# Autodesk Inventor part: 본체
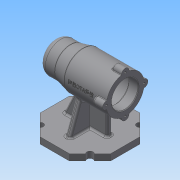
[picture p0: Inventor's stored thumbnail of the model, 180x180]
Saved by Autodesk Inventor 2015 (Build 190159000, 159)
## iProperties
Created: 2019-12
Part Number: 본체
Material: 일반
Document SubType Name: Modeling
Designer: user
Density: 1 g/cm^3
Appearance: 기본값
Mass: 268.496 g
Surface Area: 715.535 cm^2
Volume: 268.496 cm^3
Author: user
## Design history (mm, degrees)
sketch "스케치1"
  geometry: L1 (-56, 0)-(56, 0); L2 (56, 0)-(56, 21); L3 (56, 21)-(41, 21); L4 (41, 21)-(41, 24); L5 (41, 24)-(-13, 24); L6 (-13, 24)-(-13, 21); L7 (-13, 21)-(-25, 21); L8 (-25, 21)-(-25, 17.5); L9 (-25, 17.5)-(-43, 17.5); L10 (-43, 17.5)-(-43, 16); L11 (-43, 16)-(-47, 16); L12 (-47, 16)-(-47, 10.5); L13 (-47, 10.5)-(-50, 10.5); L14 (-50, 10.5)-(-50, 0); L15 (-56, 0)-(-56, 25); L16 (56, 21)-(56, 30); L17 (-56, 25)-(-31, 25); L18 (-31, 25)-(-11, 30); L19 (-11, 30)-(56, 30); 2 further points
  constraints: 38 end point, 10 perpendicular, 4 vertical, 3 point on line, 2 horizontal, 1 coincident, 1 midpoint
  dimensions: "d1" = 112 distance of L1.start L1.end; "d2" = 42 diameter of L3 L1; "d3" = 48 diameter of L5 L1; "d4" = 35 diameter of L9 L1; "d5" = 32 diameter of L11 L1; "d6" = 21 diameter of L13 L1; "d7" = 15 distance of L2.end L3.end; "d8" = 54 distance of L4.end L5.end; "d9" = 12 distance of L6.end L7.end; "d10" = 18 distance of L8.end L9.end; "d11" = 4 distance of L10.end L11.end; "d12" = 3 distance of L12.end L13.end; "d13" = 50 diameter of L15.end L1; "d14" = 60 diameter of L16.end L1; "d18" = 60 diameter of L18.end L1; "d19" = 25 distance of L15.end L17.end; "d20" = 45 horizontal distance of L18.end L15.end
revolve "회전1" sketch "스케치1" stored, may be unused: angle "d21" = 90 deg
fillet "모깎기1" dims "d22" = 3
fillet "모깎기2" dims "d23" = 3
chamfer "모따기1" distance "d24" = 1; stored, may be unused: second distance "d25" = 2, angle "d26" = 45 deg
sketch "스케치2"
  geometry: A1 r 6 centre (-30, 0) between (-29.4, 5.97) and (-29.4, -5.97); A2 r 6 centre (0, -30) between (-5.97, -29.4) and (5.97, -29.4); A3 r 6 centre (0, 30) between (5.97, 29.4) and (-5.97, 29.4); A4 r 6 centre (30, 0) between (29.4, -5.97) and (29.4, 5.97); 1 further point
  constraints: 8 point on circle, 4 centre point, 13 other
  dimensions: "d33" = 6 radius of A1; "d34" = 6 radius of A2; "d35" = 6 radius of A4; "d36" = 6 radius of A3; "d37" = 60 distance of A3.centre A2.centre; "d38" = 60 distance of A1.centre A4.centre; "d39" = 30 horizontal distance of A1.centre A3.centre; "d40" = 30 horizontal distance of A1.centre A2.centre
extrude "돌출1" join sketch "스케치2" distance "d41" = 16; taper "d42" = 0 deg
node "작업 평면1"
sketch "스케치5"
  geometry: A1 r 6 centre (0, 0) between (0.6, 5.97) and (0.6, -5.97) reference; A2 r 6 centre (30, -30) between (24.03, -29.4) and (35.97, -29.4) reference; A3 r 6 centre (60, 0) between (59.4, -5.97) and (59.4, 5.97) reference; A4 r 6 centre (30, 30) between (35.97, 29.4) and (24.03, 29.4) reference; 4 further points
  constraints: 4 coincident
hole "구멍1" sketch "스케치5" at (0, 0), (30, -30), (30, 30), (60, 0) diameter "d52" = 3.242; stored, may be unused: countersink angle "d56" = 90 deg, drill point angle "d58" = 118 deg; dims "d53" = 8, "d54" = 4, "d55" = 2, "d57" = 11
sketch "스케치6" dims "d60" = 112
  geometry: L1 (23.196, 56)-(56, 23.196); L2 (56, 23.196)-(56, -23.196); L3 (56, -23.196)-(23.196, -56); L4 (23.196, -56)-(-23.196, -56); L5 (-23.196, -56)-(-56, -23.196); L6 (-56, -23.196)-(-56, 23.196); L7 (-56, 23.196)-(-23.196, 56); L8 (-23.196, 56)-(23.196, 56); L9 (0, 0)-(0, 56); 3 further points
  constraints: 18 end point, 2 coincident, 2 midpoint, 1 vertical, 1 vertical alignment, 19 other
extrude "돌출3" join sketch "스케치6" distance "d61" = 10; taper "d62" = 0 deg
sketch "스케치8"
  geometry: L1 (-23.196, -70)-(-56, -70) reference; L2 (56, -70)-(23.196, -70) reference; L3 (36, -70)-(18.979, -23.234); L4 (-36, -70)-(-18.979, -23.234); L5 (-36, -70)-(36, -70); A1 r 30 centre (0, 0) between (18.979, -23.234) and (-18.979, -23.234) reference; A2 r 30 centre (0, 0) between (-18.979, -23.234) and (18.979, -23.234); 1 further point
  constraints: 6 end point, 4 point on circle, 2 point on line, 1 centre point, 1 coincident, 1 collinear, 1 concentric
  dimensions: "d68" = 110 deg angle of L2 L3; "d69" = 20 distance of L2.start L3.start; "d70" = 110 deg angle of L1 L4; "d71" = 20 distance of L1.end L4.start
extrude "돌출4" join sketch "스케치8" stored distance "d72" = 8; taper "d73" = 0 deg
sketch "스케치9"
  geometry: L1 (-56, -70)-(-23.196, -70) reference; L2 (11, -30)-(-40, -30) reference; L3 (31, -25)-(11, -30) reference; L4 (23.196, -70)-(56, -70) reference; L5 (38, -70)-(18.476, -28.131); L6 (-31, -70)-(-31, -30); 1 further point
  constraints: 4 end point, 4 point on line, 1 vertical
  dimensions: "d74" = 115 deg angle of L4 L5; "d75" = 18 distance of L4.end L5.start; "d76" = 25 distance from line of L1.start L6
feature "리브1" sketch "스케치9" dims "d77" = 1, "d78" = 8, "d79" = 0, "d80" = 0, "d81" = 1, "d82" = 1
sketch "스케치10"
  geometry: L1 (31, -25)-(11, -30) reference; L2 (23.196, -70)-(56, -70) reference; L3 (38, -70)-(18.476, -28.131); 1 further point
  constraints: 2 end point, 2 point on line
  dimensions: "d83" = 115 deg angle of L2 L3; "d84" = 18 distance of L2.end L3.start
feature "리브2" sketch "스케치10" dims "d85" = 1, "d86" = 8, "d87" = 0, "d88" = 0, "d89" = 1, "d90" = 1
fillet "모깎기4" dims "d94" = 10
sketch "스케치11"
  geometry: L1 (56, 23.196)-(23.196, 56) reference; L2 (-23.196, 56)-(-56, 23.196) reference; L3 (-56, -23.196)-(-23.196, -56) reference; L4 (23.196, -56)-(56, -23.196) reference; L5 (39.598, 39.598)-(-39.598, -39.598); L6 (-39.598, 39.598)-(39.598, -39.598); 5 further points
  constraints: 4 coincident, 4 end point, 4 midpoint
hole "구멍2" sketch "스케치11" at (-39.598, 39.598), (-39.598, -39.598), (39.598, -39.598), (39.598, 39.598) diameter "d95" = 10; stored, may be unused: countersink angle "d99" = 90 deg, drill point angle "d101" = 118 deg; dims "d96" = 8, "d97" = 4, "d98" = 2, "d100" = 11
fillet "모깎기6" dims "d103" = 3
fillet "모깎기7" dims "d104" = 1
fillet "모깎기8" dims "d105" = 3
fillet "모깎기9" dims "d106" = 3
fillet "모깎기10" dims "d107" = 3
fillet "모깎기12" dims "d112" = 3
fillet "모깎기13" dims "d114" = 0.3
node "작업 평면5"
sketch "스케치15"
  geometry: 2 further points
  constraints: 1 other
feature "엠보싱1" sketch "스케치15" dims "d1" = 112, "d2" = 42, "d3" = 48, "d4" = 35, "d5" = 32, "d6" = 21, "d7" = 15, "d8" = 54, "d9" = 12, "d10" = 18, "d11" = 4, "d12" = 3, "d13" = 50, "d14" = 60, "d18" = 60, "d19" = 25, "d20" = 45, "d117" = 0.5, "d118" = 0
node "솔리드1"
